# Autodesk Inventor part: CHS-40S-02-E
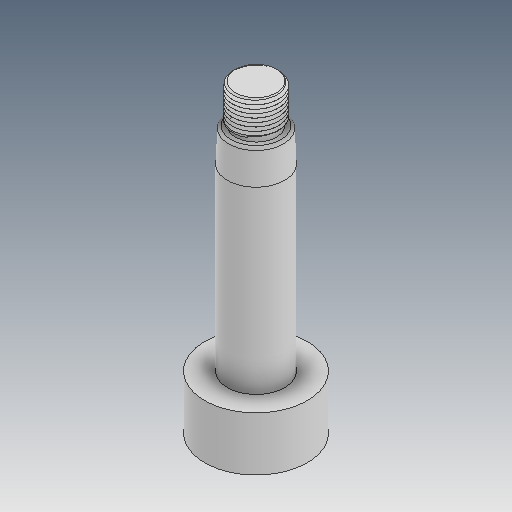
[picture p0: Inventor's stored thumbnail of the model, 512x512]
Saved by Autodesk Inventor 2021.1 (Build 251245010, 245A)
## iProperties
Created: 2019-04
Part Number: CHS-40S-02-E
Material: Ogólny
Document SubType Name: Modeling
Designer: user
Density: 1 g/cm^3
Appearance: Domyślna
Author: user
Revision Number: ÈÎºÎ
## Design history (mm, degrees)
feature "ÊäÈë1"
feature "ÊäÈë2"
node "Bryła1"
node "Bryła2"
